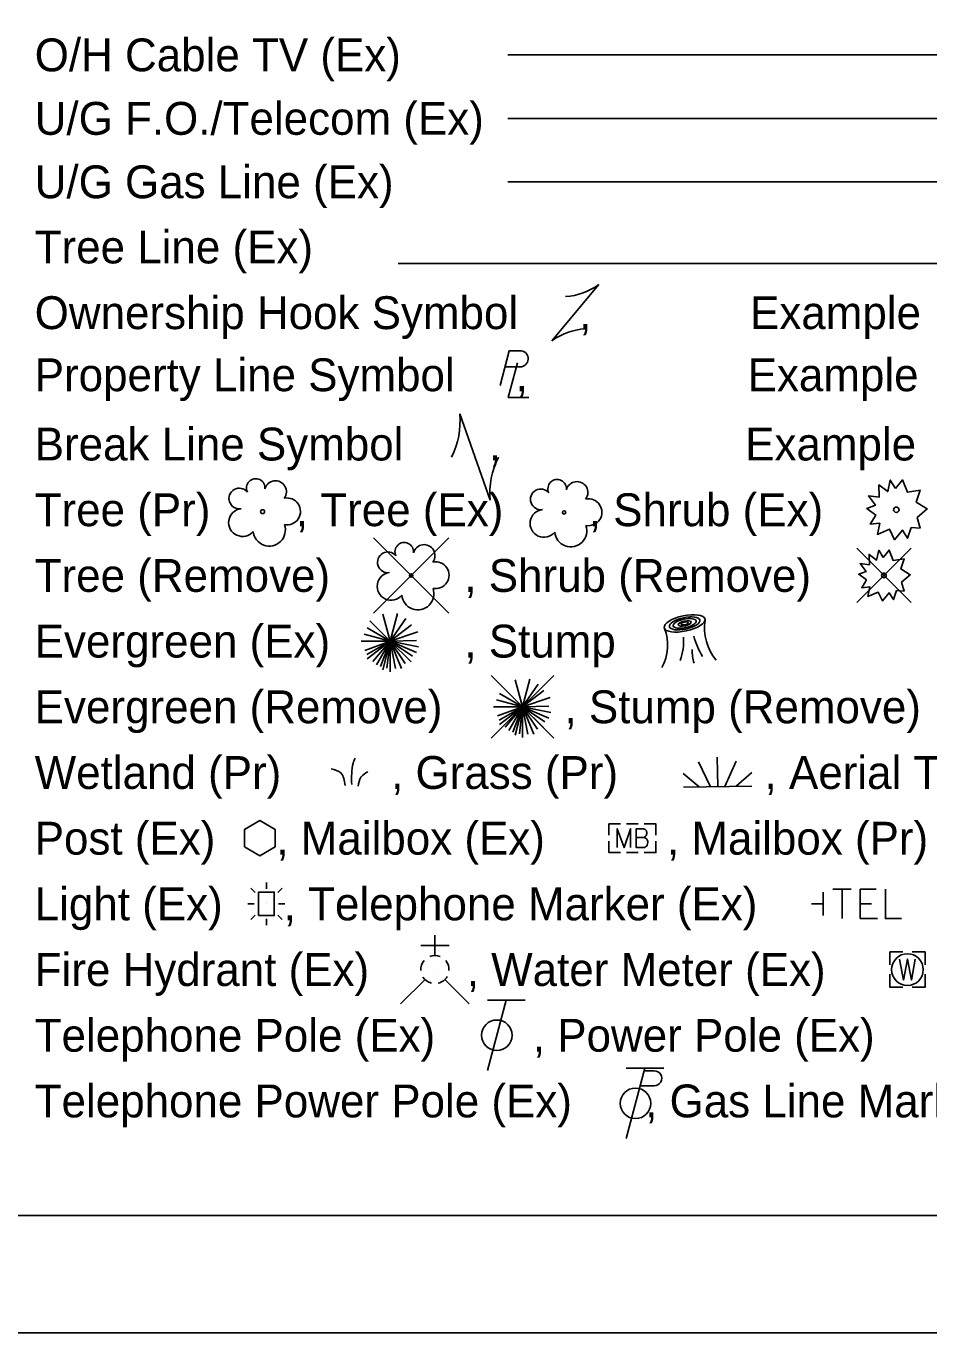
# Model space of a CAD drawing. Extents: x 0 to 34, y 0 to 22.
# Drawn here: x 7.92 to 11.77, y 0 to 5.57 of the extents above; entities that cross this region are included whole.
import ezdxf

# ---------------------------------------------------------------- set-up
doc = ezdxf.new("R2010")
doc.units = 0
for name, color, linetype in [('SH_Border', 7, 'Continuous'), ('SH_Cut_Line', 7, 'Continuous'), ('SH_Text', 7, 'Continuous'), ('UT_X_Gas', 7, 'Continuous'), ('UT_X_Overhead_Cable_TV', 7, 'Continuous'), ('UT_X_Telecom_FO', 7, 'Continuous')]:
    doc.layers.add(name, color=color, linetype=linetype)

msp = doc.modelspace()

# ---------------------------------------------------------------- linework, layer by layer
at = {"layer": 'SH_Border'}
msp.add_lwpolyline([(1.5, 21.5), (33.5, 21.5), (33.5, 0.5), (1.5, 0.5)], close=True, dxfattribs=at)
at = {"layer": 'SH_Cut_Line'}
msp.add_lwpolyline([(0, 0), (34, 0), (34, 22), (0, 22)], close=True, dxfattribs=at)
at = {"layer": 'SH_Text'}
for p, q in [((9.5076, 4.5585), (13.8576, 4.5584)), ((10.1626, 4.2285), (10.3626, 4.4685)), ((10.2626, 4.3485), (10.2626, 4.3485)), ((9.9629, 4.1175), (10.0277, 4.1175)), ((10.003, 4.0863), (10.003, 4.0863)), ((9.7702, 3.917), (9.9002, 3.5488)), ((9.8352, 3.7329), (9.8352, 3.7329)), ((9.403, 3.3888), (9.7238, 3.068)), ((9.7238, 3.3888), (9.403, 3.068)), ((11.4621, 3.3443), (11.6939, 3.1126)), ((11.6939, 3.3443), (11.4621, 3.1126)), ((9.5634, 3.2284), (9.5634, 3.2284)), ((11.578, 3.2285), (11.578, 3.2285)), ((9.4739, 2.9482), (9.443, 3.0636)), ((9.4739, 2.9482), (9.5053, 3.0657)), ((9.4739, 2.9482), (9.3866, 3.0354)), ((9.4739, 2.9482), (9.5403, 3.0454)), ((9.4739, 2.9482), (9.5653, 3.0184)), ((9.4739, 2.9482), (9.3635, 2.9778)), ((9.4739, 2.9482), (9.3762, 3.0057)), ((9.4739, 2.9482), (9.5923, 2.9884)), ((9.3505, 2.9482), (9.4739, 2.9482)), ((9.4739, 2.9482), (9.3666, 2.9092)), ((9.4739, 2.9482), (9.3743, 2.8912)), ((9.4739, 2.9482), (9.3762, 2.8734)), ((9.4739, 2.9482), (9.4003, 2.8616)), ((9.4739, 2.9482), (9.4159, 2.8479)), ((9.4739, 2.9482), (9.4323, 2.8397)), ((9.4739, 2.9482), (9.4423, 2.8268)), ((9.4739, 2.9482), (9.4603, 2.8334)), ((9.4739, 2.9482), (9.5866, 2.9505)), ((9.4739, 2.8172), (9.4739, 2.9482)), ((9.4739, 2.9482), (9.4969, 2.8323)), ((9.4739, 2.9482), (9.5222, 2.8315)), ((9.4739, 2.9482), (9.5373, 2.8534)), ((9.4739, 2.9482), (9.5636, 2.8602)), ((9.4739, 2.9482), (9.5694, 2.8844)), ((9.4739, 2.9482), (9.5855, 2.8997)), ((9.4739, 2.9482), (9.5946, 2.9243)), ((10.7475, 2.9485), (10.7475, 2.9485)), ((9.9043, 2.8021), (10.1716, 2.5348)), ((10.1716, 2.8021), (9.9043, 2.5348)), ((10.0379, 2.6685), (10.0693, 2.7859)), ((10.0379, 2.6685), (9.9506, 2.7556)), ((10.0379, 2.6685), (10.007, 2.7838)), ((10.0379, 2.6685), (10.1043, 2.7656)), ((10.0379, 2.6685), (10.1293, 2.7386)), ((10.0379, 2.6685), (9.9276, 2.6981)), ((10.0379, 2.6685), (9.9402, 2.7259)), ((10.0379, 2.6685), (10.1563, 2.7086)), ((9.9145, 2.6685), (10.0379, 2.6685)), ((10.0379, 2.6685), (9.9306, 2.6294)), ((10.0379, 2.6685), (9.9383, 2.6114)), ((10.0379, 2.6685), (9.9402, 2.5936)), ((10.0379, 2.6685), (9.9643, 2.5818)), ((10.0379, 2.6685), (9.9799, 2.5681)), ((10.0379, 2.6685), (9.9963, 2.56)), ((10.0379, 2.6685), (10.0063, 2.5471)), ((10.0379, 2.6685), (10.0243, 2.5537)), ((10.0379, 2.6685), (10.1506, 2.6708)), ((10.0379, 2.5375), (10.0379, 2.6685)), ((10.0379, 2.6685), (10.0609, 2.5526)), ((10.0379, 2.6685), (10.0862, 2.5518)), ((10.0379, 2.6685), (10.1013, 2.5736)), ((10.0379, 2.6685), (10.1276, 2.5804)), ((10.0379, 2.6685), (10.1334, 2.6046)), ((10.0379, 2.6685), (10.1495, 2.6199)), ((10.0379, 2.6685), (10.1586, 2.6445)), ((10.0379, 2.6685), (10.0379, 2.6685)), ((10.8695, 2.3285), (10.8676, 2.454)), ((10.8395, 2.3281), (10.7874, 2.4341)), ((10.8995, 2.3289), (10.9484, 2.4365)), ((10.7908, 2.3273), (10.7225, 2.3844)), ((10.9482, 2.3297), (11.0148, 2.3887)), ((10.7234, 2.3263), (11.0156, 2.3306)), ((10.4807, 2.1696), (10.5307, 2.1696)), ((10.5062, 2.1085), (10.5062, 2.1085)), ((10.4807, 2.0474), (10.5307, 2.0474)), ((8.8983, 1.8769), (8.8798, 1.8956)), ((8.9466, 1.8925), (8.9466, 1.9191)), ((9.0133, 1.8956), (8.9947, 1.8769)), ((11.3192, 1.7785), (11.3192, 1.8785)), ((8.8944, 1.8288), (8.8678, 1.8288)), ((8.9466, 1.8285), (8.9466, 1.8285)), ((9.0253, 1.8288), (8.9987, 1.8288)), ((11.3192, 1.8285), (11.2695, 1.8285)), ((8.8983, 1.7801), (8.8798, 1.7613)), ((8.9466, 1.7645), (8.9466, 1.7379)), ((9.0133, 1.7613), (8.9947, 1.7801)), ((9.6646, 1.6086), (9.6646, 1.6946)), ((9.7246, 1.6516), (9.6046, 1.6516)), ((9.6224, 1.5061), (9.5184, 1.4021)), ((9.6647, 1.5485), (9.6647, 1.5485)), ((9.6647, 1.5485), (9.6647, 1.5485)), ((9.7069, 1.5061), (9.8109, 1.4021)), ((11.6783, 1.5485), (11.6783, 1.5485)), ((9.9686, 1.4185), (9.8882, 1.1185)), ((10.0486, 1.4185), (9.8886, 1.4185)), ((10.5594, 1.1283), (10.4791, 0.8283)), ((10.6394, 1.1283), (10.4794, 1.1283)), ((10.5564, 1.117), (10.5989, 1.117)), ((10.5393, 1.0533), (10.5989, 1.0533))]:
    msp.add_line(p, q, dxfattribs=at)
for points in [[(9.9419, 4.0379), (9.981, 4.1861), (10.0326, 4.1861)], [(10.0163, 4.1343), (9.9767, 3.9865), (10.0641, 3.9865)], [(11.6267, 3.599), (11.657, 3.6357), (11.6777, 3.5831), (11.7323, 3.5921), (11.7154, 3.5415), (11.7627, 3.5117), (11.7198, 3.475), (11.7323, 3.4293), (11.6947, 3.4327), (11.6784, 3.3871), (11.657, 3.4216), (11.6231, 3.3808), (11.6017, 3.4251), (11.5507, 3.4036), (11.5602, 3.4507), (11.5197, 3.4466), (11.5433, 3.4861), (11.5049, 3.5145), (11.5418, 3.5276), (11.5115, 3.5678), (11.5581, 3.5623), (11.5566, 3.6142), (11.5942, 3.5858), (11.6046, 3.6351), (11.6267, 3.599)], [(11.5744, 3.3054), (11.6001, 3.3366), (11.6177, 3.2919), (11.6641, 3.2995), (11.6498, 3.2565), (11.6899, 3.2312), (11.6535, 3.2), (11.6641, 3.1612), (11.6321, 3.1641), (11.6183, 3.1253), (11.6001, 3.1547), (11.5713, 3.12), (11.5531, 3.1576), (11.5097, 3.1394), (11.5179, 3.1794), (11.4834, 3.1758), (11.5035, 3.2094), (11.4708, 3.2336), (11.5022, 3.2448), (11.4764, 3.2789), (11.516, 3.2742), (11.5148, 3.3184), (11.5468, 3.2942), (11.5556, 3.3361), (11.5744, 3.3054)], [(8.8534, 2.071), (8.9183, 2.0335), (8.9832, 2.071), (8.9832, 2.146), (8.9183, 2.1835), (8.8534, 2.146), (8.8534, 2.071)], [(10.4062, 2.1211), (10.4062, 2.1696), (10.4547, 2.1696)], [(10.4414, 2.0685), (10.4414, 2.1485), (10.4704, 2.0685), (10.4981, 2.1485), (10.4981, 2.0685)], [(10.5573, 2.1119), (10.5605, 2.1151), (10.5624, 2.117), (10.5636, 2.1189), (10.5643, 2.1201), (10.5655, 2.1226), (10.5662, 2.1245), (10.5674, 2.1289), (10.5674, 2.1308), (10.5674, 2.1333), (10.5668, 2.1371), (10.5655, 2.1403), (10.5636, 2.1428), (10.5605, 2.1453), (10.558, 2.1466), (10.5567, 2.1472), (10.5536, 2.1485), (10.5227, 2.1485), (10.5227, 2.0685), (10.5573, 2.0685), (10.5617, 2.071), (10.5655, 2.0741), (10.5687, 2.0792), (10.5706, 2.0848), (10.5712, 2.0905), (10.5712, 2.0943), (10.5699, 2.0981), (10.5674, 2.1037), (10.5643, 2.1075), (10.5573, 2.1119), (10.5227, 2.1119)], [(10.5566, 2.1696), (10.6062, 2.1696), (10.6062, 2.1211)], [(10.4547, 2.0474), (10.4062, 2.0474), (10.4062, 2.0959)], [(10.6062, 2.0959), (10.6062, 2.0474), (10.5566, 2.0474)], [(11.3601, 1.8906), (11.4378, 1.8906)], [(11.3994, 1.8906), (11.3994, 1.7656)], [(11.5451, 1.8906), (11.4772, 1.8906), (11.4772, 1.7656), (11.55, 1.7656)], [(11.5844, 1.8906), (11.5844, 1.7656), (11.6524, 1.7656)], [(11.4772, 1.8285), (11.5254, 1.8285)], [(11.6583, 1.6235), (11.6033, 1.6235), (11.6033, 1.5685)], [(11.7533, 1.5685), (11.7533, 1.6235), (11.6983, 1.6235)], [(11.6449, 1.5935), (11.6616, 1.5035), (11.6783, 1.5935), (11.6949, 1.5035), (11.7116, 1.5935)], [(11.6033, 1.5285), (11.6033, 1.4735), (11.6583, 1.4735)], [(11.6983, 1.4735), (11.7533, 1.4735), (11.7533, 1.5285)]]:
    msp.add_lwpolyline(points, dxfattribs=at)
msp.add_lwpolyline([(8.9133, 1.7785), (8.9798, 1.7785), (8.9798, 1.8785), (8.9133, 1.8785)], close=True, dxfattribs=at)
for centre, radius in [((11.6309, 3.5085), 0.0115), ((8.9304, 3.5004), 0.0084), ((10.215, 3.4969), 0.0072), ((9.5634, 3.2284), 0.0072), ((11.578, 3.2285), 0.00979), ((11.6783, 1.5485), 0.0675), ((9.9284, 1.2685), 0.065), ((10.5192, 0.9783), 0.065)]:
    msp.add_circle(centre, radius, dxfattribs=at)
for centre, radius, start, end in [((10.2045, 4.6834), 0.2668, 273.6945, 306.337), ((10.3207, 4.0135), 0.2668, 93.6945, 126.337), ((10.0274, 4.152), 0.0345, 270.471, 81.3281), ((9.4382, 3.8846), 0.3335, 332.9422, 5.5848), ((10.2321, 3.5812), 0.3335, 152.9422, 185.5848), ((8.9009, 3.6014), 0.0395, 354.0047, 205.9741), ((8.9852, 3.5852), 0.0466, 323.83, 165.0376), ((10.1855, 3.5979), 0.0395, 354.0047, 205.9741), ((10.2698, 3.5818), 0.0466, 323.83, 165.0376), ((8.8311, 3.5563), 0.0441, 39.0625, 279.5412), ((10.1157, 3.5528), 0.0441, 39.0625, 279.5412), ((8.8448, 3.4539), 0.0592, 96.1722, 320.5737), ((9.0342, 3.5014), 0.0574, 259.1453, 101.4596), ((10.1294, 3.4504), 0.0592, 96.1722, 320.5737), ((10.3188, 3.498), 0.0574, 259.1453, 101.4596), ((8.9588, 3.4222), 0.0685, 184.9476, 19.4572), ((10.2434, 3.4188), 0.0685, 184.9476, 19.4572), ((9.5339, 3.3295), 0.0395, 354.0047, 205.9741), ((9.6182, 3.3133), 0.0466, 323.83, 165.0376), ((9.4641, 3.2844), 0.0441, 39.0625, 279.5412), ((9.6672, 3.2295), 0.0574, 259.1453, 101.4596), ((9.4778, 3.182), 0.0592, 96.1722, 320.5737), ((9.5918, 3.1503), 0.0685, 184.9476, 19.4572), ((11.0278, 3.0055), 0.2146, 171.4106, 219.9194), ((10.4559, 2.9312), 0.2001, 331.5338, 20.9269), ((10.4717, 2.9497), 0.2527, 340.7938, 3.5481), ((11.0729, 3.0513), 0.316, 194.9653, 212.1216), ((10.9428, 2.9085), 0.1819, 178.7926, 197.1224), ((9.6647, 1.5485), 0.06, 140.021, 184.0629), ((9.6647, 1.5485), 0.06, 68.1395, 112.038), ((9.6647, 1.5485), 0.06, 356.0165, 39.9889), ((9.6647, 1.5485), 0.06, 211.8788, 255.8479), ((9.6647, 1.5485), 0.06, 283.8239, 329.9097), ((10.5995, 1.0852), 0.0319, 268.8767, 91.1233)]:
    msp.add_arc(centre, radius, start, end, dxfattribs=at)
for major_axis in [(0.0868, 0.0187), (0.0651, 0.0141), (0.0488, 0.0105), (0.0275, 0.0059), (0.0154, 0.0033)]:
    msp.add_ellipse((10.7288, 3.024), major_axis=major_axis, ratio=0.36865, dxfattribs=at)
for points in [[(9.2226, 2.404), (9.264, 2.3864), (9.2818, 2.333)], [(9.3099, 2.337), (9.3099, 2.3844), (9.3159, 2.4288), (9.3247, 2.4495)], [(9.3377, 2.3299), (9.3495, 2.3683), (9.379, 2.392)]]:
    msp.add_spline(points, degree=3, dxfattribs=at)
at = {"layer": 'UT_X_Gas'}
msp.add_line((9.9753, 4.9062), (13.8753, 4.9062), dxfattribs=at)
at = {"layer": 'UT_X_Overhead_Cable_TV'}
msp.add_line((9.9753, 5.4472), (13.8753, 5.4472), dxfattribs=at)
at = {"layer": 'UT_X_Telecom_FO'}
msp.add_line((9.9753, 5.1767), (13.8753, 5.1767), dxfattribs=at)

# ---------------------------------------------------------------- texts
at = {"layer": 'SH_Text'}
for s, p in [('O/H Cable TV (Ex)', (7.9591, 5.3772)), ('U/G F.O./Telecom (Ex)', (7.9591, 5.1067)), ('U/G Gas Line (Ex)', (7.9591, 4.8362)), ('Tree Line (Ex)', (7.9591, 4.5585)), ('Ownership Hook Symbol     ,             Example', (7.9591, 4.2785)), ('Property Line Symbol     ,                  Example', (7.9591, 4.0138)), ('Break Line Symbol       ,                    Example', (7.9591, 3.7185)), ('Tree (Pr)       , Tree (Ex)       , Shrub (Ex)', (7.9591, 3.4385)), ('Tree (Remove)           , Shrub (Remove)', (7.9591, 3.1585)), ('Evergreen (Ex)           , Stump ', (7.9591, 2.8785)), ('Evergreen (Remove)          , Stump (Remove)', (7.9591, 2.5985)), ('Wetland (Pr)         , Grass (Pr)            , Aerial Target    ', (7.9591, 2.3185)), ('Post (Ex)     , Mailbox (Ex)          , Mailbox (Pr)', (7.9591, 2.0385)), ('Light (Ex)     , Telephone Marker (Ex)     ', (7.9591, 1.7585)), ('Fire Hydrant (Ex)        , Water Meter (Ex)', (7.9591, 1.4785)), ('Telephone Pole (Ex)        , Power Pole (Ex)        , ', (7.9591, 1.1985)), ('Telephone Power Pole (Ex)      , Gas Line Marker      , Gas Valve (Ex)', (7.9591, 0.9185))]:
    msp.add_text(s, height=0.14, dxfattribs=at).set_placement(p)

doc.saveas('drawing.dxf')
